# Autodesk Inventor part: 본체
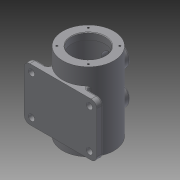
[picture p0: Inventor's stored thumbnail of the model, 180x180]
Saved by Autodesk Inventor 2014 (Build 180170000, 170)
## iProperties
Created: 2014-12
Part Number: 본체
Material: 일반
Document SubType Name: Modeling
Designer: Owner
Density: 1 g/cm^3
Appearance: 기본값
Author: Owner
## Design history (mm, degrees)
sketch "스케치1"
  geometry: C1 r 46 at (0, 0); 1 further point
  constraints: 1 centre point, 1 coincident
  dimensions: "d0" = 92 diameter of C1
extrude "돌출1" new body sketch "스케치1" distance "d1" = 140; taper "d2" = 0 deg
sketch "스케치2"
  geometry: C1 r 46 at (0, 0) reference; C2 r 30 at (0, 0)
  constraints: 1 centre point, 1 coincident
  dimensions: "d3" = 60 diameter of C2
extrude "돌출2" cut sketch "스케치2" stored distance "d4" = 140; taper "d5" = 0 deg
node "작업 평면1"
sketch "스케치3"
  geometry: C1 r 37.5 at (0, 0); 1 further point
  constraints: 1 centre point, 1 coincident
  dimensions: "d7" = 75 diameter of C1
extrude "돌출3" cut sketch "스케치3" distance "d8" = 116; taper "d9" = 0 deg
node "작업 평면2"
sketch "스케치4"
  geometry: L1 (-65, 110)-(65, 110); L2 (65, 110)-(65, 15); L3 (65, 15)-(-65, 15); L4 (-65, 15)-(-65, 110); L5 (46, 140)-(-46, 140) reference; L6 (-46, 0)-(46, 0) reference; 3 further points
  constraints: 8 end point, 2 midpoint, 2 parallel, 1 horizontal, 1 perpendicular, 1 vertical alignment
  dimensions: "d11" = 130 distance of L2.end L3.end; "d12" = 95 distance of L1.end L2.end; "d13" = 15 distance between parallel lines of L3 L6
extrude "돌출4" join sketch "스케치4" distance "d14" = 12; taper "d15" = 0 deg
node "작업 평면3"
sketch "스케치5"
  geometry: L1 (25.923, 110)-(-25.923, 110) reference; L2 (-25.923, 110)-(-25.923, 15) reference; L3 (-25.923, 15)-(25.923, 15) reference; L4 (25.923, 15)-(25.923, 110) reference; L5 (46, 140)-(-46, 140) reference; L6 (-46, 0)-(46, 0) reference; C1 r 20 at (0, 100); C2 r 20 at (0, 40); 2 further points
  constraints: 2 centre point, 1 midpoint, 1 vertical alignment
  dimensions: "d17" = 40 diameter of C1; "d18" = 40 diameter of C2; "d19" = 40 distance from line of C1.centre L5; "d20" = 60 distance of C2.centre C1.centre; "d21" = 40 distance from line of L6 C2.centre
extrude "돌출5" join sketch "스케치5" stored distance "d22" = 0; taper "d23" = 0 deg
sketch "스케치6"
  geometry: C1 r 20 at (0, 0) reference; 2 further points
  constraints: 1 coincident
sketch "스케치7"
  geometry: C1 r 20 at (0, 0) reference; 2 further points
  constraints: 1 coincident
hole "구멍1" sketch "스케치6" diameter "d24" = 25; stored, may be unused: countersink angle "d28" = 90 deg, drill point angle "d30" = 118 deg; dims "d25" = 6, "d26" = 30, "d27" = 8, "d29" = 8
hole "구멍2" sketch "스케치7" diameter "d31" = 25; stored, may be unused: countersink angle "d35" = 90 deg, drill point angle "d37" = 118 deg; dims "d32" = 6, "d33" = 30, "d34" = 8, "d36" = 8
sketch "스케치8"
  geometry: L1 (0, 0)-(28.284, 28.284); L2 (0, 0)-(40, 0); C1 r 46 at (0, 0) reference; 1 further point
  constraints: 4 end point, 1 coincident, 1 equal length, 1 horizontal
  dimensions: "d38" = 40 distance of L1.start L1.end; "d39" = 45 deg angle of L2 L1
hole "구멍3" sketch "스케치8" at (28.284, 28.284) diameter "d40" = 3.242; stored, may be unused: countersink angle "d44" = 90 deg, drill point angle "d46" = 118 deg; dims "d41" = 8, "d42" = 30, "d43" = 8, "d45" = 10
node "작업 평면4"
sketch "스케치9"
  geometry: L1 (25.923, -110)-(65, -110) reference; L2 (65, -110)-(65, -15) reference; C1 r 5.5 at (52, -97.5); 1 further point
  constraints: 1 centre point
  dimensions: "d50" = 11 diameter of C1; "d51" = 12.5 distance from line of C1.centre L1; "d52" = 13 distance from line of L2 C1.centre
extrude "돌출6" cut sketch "스케치9" distance "d53" = 12; taper "d54" = 0 deg
node "작업 평면5"
sketch "스케치10"
  geometry: L1 (65, -110)-(65, -15) reference; C1 r 5.5 at (52, -97.5) reference; 2 further points
  constraints: 1 other
  dimensions: "d55" = 35 vertical distance of point (57, -62.5) C1.centre; "d56" = 8 distance from line of point (57, -62.5) L1
feature "엠보싱1" sketch "스케치10" dims "d57" = 1, "d58" = 0
fillet "모깎기1" dims "d59" = 5
fillet "모깎기2" dims "d60" = 10
chamfer "모따기1" distance "d61" = 1; stored, may be unused: second distance "d62" = 2, angle "d63" = 45 deg
fillet "모깎기3" dims "d64" = 3
fillet "모깎기4" dims "d65" = 3
fillet "모깎기5" dims "d66" = 3
node "솔리드1"
pattern_circular "원형 패턴1" dims angle "d48" = 360 deg
mirror "대칭1"
mirror "대칭2"
mirror "대칭3"
node "투영된 루프1"
node "투영된 루프2"
other parameters: "d6" = 12, "d16" = 56
